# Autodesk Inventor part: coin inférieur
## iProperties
Shininess: 64.0
Length Units: 11269
Angle Units: 11279
Time Units: 11290
Mass Units: 11283
Length Display Precision: 3
Angle Display Precision: 2
Compacted: True
Part Number: coin inférieur
Document SubType Name: Modeling
Created: 2005-01
Material: Par défaut
Designer: LEGERET Philippe
Density: 0.0
Volumn: 0.0
Area: 0.0
PropertySet Name: Model Information
Control State: 0
Master: False
Checked Out: False
Author: LEGERET Philippe
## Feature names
1. Extrusion1
2. Extrusion2
3. Extrusion3
4. Extrusion4
